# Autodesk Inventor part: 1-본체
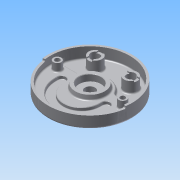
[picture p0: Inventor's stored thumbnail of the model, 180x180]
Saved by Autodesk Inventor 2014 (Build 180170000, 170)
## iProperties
Created: 2015-06
Part Number: 1-본체
Material: 알루미늄 6061
Document SubType Name: Modeling
Designer: Administrator
Density: 2.71 g/cm^3
Appearance: 알루미늄 - 평지
Mass: 1076.56 g
Surface Area: 1039.59 cm^2
Volume: 397.256 cm^3
Author: Administrator
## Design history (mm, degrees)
sketch "스케치1"
  geometry: C1 r 95 at (0, 0); 1 further point
  constraints: 1 centre point, 1 coincident
  dimensions: "d0" = 190 diameter of C1
extrude "돌출1" new body sketch "스케치1" distance "d1" = 32; taper "d2" = 0 deg
sketch "스케치2"
  geometry: C1 r 95 at (0, 0) reference; C2 r 90 at (0, 0)
  constraints: 1 centre point, 1 coincident
  dimensions: "d3" = 180 diameter of C2
extrude "돌출2" cut sketch "스케치2" distance "d4" = 18; taper "d5" = 0 deg
sketch "스케치3"
  geometry: C1 r 90 at (0, 0) reference; C2 r 35 at (0, 0)
  constraints: 1 centre point, 1 coincident
  dimensions: "d6" = 70 diameter of C2
extrude "돌출3" join sketch "스케치3" distance "d7" = 10; taper "d8" = -10 deg
sketch "스케치4"
  geometry: L1 (-88.566, 16)-(-38.833, 16); L2 (38.833, 16)-(88.566, 16); C1 r 35 at (0, 0) reference; A1 r 90 centre (0, 0) between (-88.566, 16) and (88.566, 16) reference; A2 r 42 centre (0, 0) between (38.833, 16) and (-38.833, 16)
  constraints: 4 end point, 4 point on circle, 2 collinear, 1 centre point, 1 coincident, 1 horizontal
  dimensions: "d9" = 84 diameter of A2; "d10" = 16 distance from line of C1.centre L1
extrude "돌출4" cut sketch "스케치4" distance "d11" = 7; taper "d12" = 0 deg
sketch "스케치5"
  geometry: L1 (0, 0)-(-95, 0); L2 (0, 0)-(95, 0); L3 (0, 0)-(-89.124, -12.526); L4 (0, 0)-(89.124, -12.526); L5 (-89.124, -12.526)-(-94.075, -13.221); L6 (89.124, -12.526)-(94.075, -13.221); A1 r 90 centre (0, 0) between (-89.124, -12.526) and (89.124, -12.526) reference; A2 r 95 centre (0, 0) between (-95, 0) and (95, 0) reference; A3 r 95 centre (0, 0) between (-94.075, -13.221) and (94.075, -13.221)
  constraints: 12 end point, 8 point on circle, 1 centre point, 1 coincident, 1 collinear, 1 horizontal
  dimensions: "d14" = 8 deg angle of L1 L3; "d15" = 8 deg angle of L2 L4; "d16" = 8 deg angle of L2 L6; "d17" = 8 deg angle of L1 L5
extrude "돌출5" cut sketch "스케치5" distance "d18" = 5; taper "d19" = 0 deg
sketch "스케치7"
  geometry: C1 r 95 at (0, 0) reference; C2 r 26 at (0, 0)
  constraints: 1 centre point, 1 coincident
  dimensions: "d28" = 52 diameter of C2
extrude "돌출6" join sketch "스케치7" distance "d29" = 12; taper "d30" = -15 deg
hole "구멍1" diameter "d33" = 23; stored, may be unused: countersink angle "d37" = 90 deg, drill point angle "d39" = 118 deg; dims "d31" = 10, "d32" = 10, "d34" = 6, "d35" = 50, "d36" = 15, "d38" = 8
sketch "스케치8"
  geometry: C1 r 15 at (40, 52); C2 r 15 at (-40, 52); A1 r 42 centre (0, 0) between (38.833, 16) and (-38.833, 16) reference
  constraints: 2 centre point, 1 equal radius, 1 horizontal alignment
  dimensions: "d40" = 80 distance of C1.centre C2.centre; "d41" = 40 horizontal distance of A1.centre C2.centre; "d42" = 52 vertical distance of A1.centre C1.centre; "d44" = 30 diameter of C2
extrude "돌출7" join sketch "스케치8" distance "d45" = 25; taper "d46" = 0 deg
sketch "스케치10"
  geometry: C1 r 15 at (0, 0) reference; C2 r 15 at (80, 0) reference; C3 r 10 at (0, 0); C4 r 10 at (80, 0); 1 further point
  constraints: 2 centre point, 2 coincident, 1 equal radius
  dimensions: "d54" = 20 diameter of C3
extrude "돌출8" cut sketch "스케치10" stored distance "d55" = 25; taper "d56" = 0 deg
sketch "스케치11"
  geometry: L1 (-86, 13.748)-(-86, -13.748); L2 (-74, -13.748)-(-74, 13.748); L3 (-13.748, 6)-(13.748, 6); L4 (-13.748, -6)-(13.748, -6); C1 r 10 at (0, 0) reference; C2 r 10 at (-80, 0) reference; A1 r 15 centre (0, 0) between (-13.748, 6) and (13.748, 6) reference; A2 r 15 centre (-80, 0) between (-86, 13.748) and (-86, -13.748) reference; 1 further point
  constraints: 8 end point, 8 point on circle, 2 parallel, 1 perpendicular, 1 vertical
  dimensions: "d57" = 6 distance from line of L3 C1.centre; "d58" = 12 distance between parallel lines of L4 L3; "d59" = 6 distance from line of L2 C2.centre; "d60" = 12 distance between parallel lines of L1 L2
extrude "돌출9" cut sketch "스케치11" distance "d61" = 3; taper "d62" = 0 deg
sketch "스케치12"
  geometry: L1 (88.566, 16)-(38.833, 16) reference; L2 (-41, -19)-(-59, -19); L3 (41, -19)-(59, -19); A1 r 90 centre (0, 0) between (-88.566, 16) and (88.566, 16) reference; A2 r 59 centre (0, -19) between (-59, -19) and (59, -19); A3 r 41 centre (0, -19) between (-41, -19) and (41, -19)
  constraints: 4 end point, 4 point on circle, 2 centre point, 1 coincident, 1 collinear, 1 parallel, 1 vertical alignment
  dimensions: "d67" = 19 distance of A2.centre A1.centre; "d68" = 59 radius of A2; "d69" = 41 radius of A3; "d70" = 19 distance from line of A1.centre L3; "d71" = 19 distance from line of A1.centre L2
extrude "돌출10" cut sketch "스케치12" distance "d72" = 7; taper "d73" = 0 deg
sketch "스케치13"
  geometry: L1 (-59, -19)-(-41, -19) reference; L2 (41, -19)-(59, -19) reference; L3 (-59, -14)-(-41, -14); L4 (41, -14)-(59, -14); L5 (-59, -19)-(-59, -14); L6 (-41, -19)-(-41, -14); L7 (41, -19)-(41, -14); L8 (59, -19)-(59, -14); A1 r 59 centre (0, -19) between (-59, -19) and (59, -19) reference; A2 r 41 centre (0, -19) between (-41, -19) and (41, -19) reference; 3 further points
  constraints: 12 end point, 5 equal length, 4 tangent, 2 horizontal alignment, 2 midpoint, 1 perpendicular, 4 other
  dimensions: "d74" = 5 distance between parallel lines of L4 L2; "d75" = 5 distance between parallel lines of L1 L3
extrude "돌출11" cut sketch "스케치13" distance "d76" = 7; taper "d77" = 0 deg
sketch "스케치14"
  geometry: C1 r 9 at (-74, 0); C2 r 9 at (74, 0); A1 r 90 centre (0, 0) between (-88.566, 16) and (88.566, 16) reference
  constraints: 2 centre point, 2 horizontal alignment, 1 equal radius
  dimensions: "d78" = 18 diameter of C1; "d79" = 148 distance of C2.centre C1.centre; "d80" = 74 distance of A1.centre C2.centre
extrude "돌출12" join sketch "스케치14" distance "d81" = 18; taper "d82" = 0 deg
sketch "스케치15"
  geometry: C1 r 9 at (-74, 0) reference; C2 r 9 at (74, 0) reference; 2 further points
  constraints: 2 coincident
hole "구멍3" sketch "스케치15" at (-74, 0), (74, 0) diameter "d83" = 11; stored, may be unused: countersink angle "d87" = 90 deg, drill point angle "d89" = 118 deg; dims "d84" = 6, "d85" = 18, "d86" = 11, "d88" = 8
fillet "모깎기1" dims "d90" = 10
fillet "모깎기2" dims "d91" = 10
chamfer "모따기1" distance "d92" = 1; stored, may be unused: second distance "d93" = 2, angle "d94" = 45 deg
chamfer "모따기2" distance "d95" = 1; stored, may be unused: second distance "d96" = 2, angle "d97" = 45 deg
fillet "모깎기3" dims "d98" = 1
fillet "모깎기4" dims "d99" = 0.3
sketch "스케치16"
  geometry: C1 r 95 at (0, 0) reference; C2 r 68 at (0, 0)
  constraints: 1 centre point, 1 coincident, 1 other
  dimensions: "d100" = 136 diameter of C2
feature "엠보싱1" sketch "스케치16" dims "d101" = 0.5, "d102" = 0
fillet "모깎기5" dims "d103" = 3, "d107" = 5
fillet "모깎기6" dims "d104" = 3
fillet "모깎기7" dims "d105" = 3
fillet "모깎기8" dims "d106" = 3
node "솔리드1"
node "투영된 루프1"
node "투영된 루프2"
